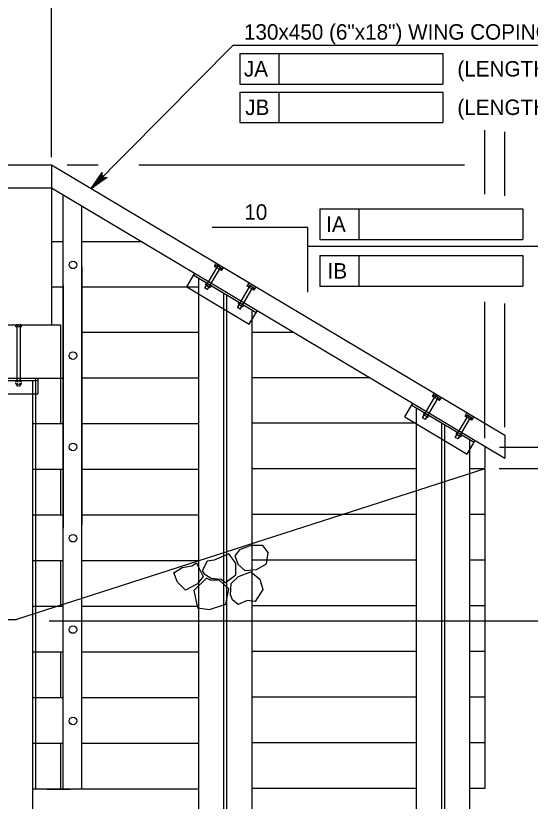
# Model space of a CAD drawing. Extents: x 635440 to 640306, y 296653 to 298484.
# Drawn here: x 639686.1 to 639785.9, y 297346.1 to 297498.4 of the extents above; entities that cross this region are included whole.
import ezdxf

# ---------------------------------------------------------------- set-up
doc = ezdxf.new("R2010")
doc.units = 0
for name, color, linetype in [('3', 7, 'Continuous'), ('4', 7, 'Continuous'), ('5', 7, 'Continuous'), ('8', 7, 'Continuous')]:
    doc.layers.add(name, color=color, linetype=linetype)

# ---------------------------------------------------------------- blocks, each defined once
blk = doc.blocks.new('ROCK')
at = {"layer": '4'}
for points in [[(2.36725, 1.088), (2.2065, 0.82625), (2.378625, 0.506625), (2.66975, 0.3095), (3.128875, 0.403375), (3.48475, 0.6775), (3.4915, 1.123375), (3.25625, 1.36725), (2.783625, 1.308375)], [(1.10175, -0.02725), (1.4015, -0.159125), (1.78825, -0.148875), (1.980875, -0.266), (2.343375, 0.09475), (2.27875, 0.5505), (1.969375, 0.883), (1.4225, 0.553625), (1.152875, 0.479), (1.0105, 0.082)], [(0.74675, 0.359875), (0.882, 0.16), (1.072875, -0.144), (0.892, -0.457375), (0.448125, -0.758625), (0.1, -0.49325), (-0.095, -0.146375), (0.202875, 0.1025), (0.579125, 0.219875)], [(2.231375, -0.71725), (2.2025, -0.266375), (2.45475, 0.037125), (2.9085, 0.28875), (3.2995, 0.047625), (3.46875, -0.344), (3.231625, -0.855), (2.92, -0.860375), (2.5765, -1.054625), (2.340375, -0.904375)], [(1.2085, -0.192875), (0.778375, -0.737625), (1.008375, -1.391375), (1.48725, -1.396875), (2.09825, -1.106625), (2.133375, -0.486375), (1.723125, -0.203375), (1.37425, -0.239875)]]:
    blk.add_lwpolyline(points, close=True, dxfattribs=at)

msp = doc.modelspace()

# ---------------------------------------------------------------- linework, layer by layer
at = {"layer": '3'}
for p, q in [((639669.62, 297469.49), (639693.04, 297469.49)), ((639693.04, 297469.49), (639780.97, 297417.06)), ((639693.04, 297469.49), (639693.04, 297465.06)), ((639647.14, 297465.06), (639693.04, 297465.06)), ((639693.04, 297465.06), (639780.97, 297412.63)), ((639693.04, 297465.06), (639693.04, 297438.49)), ((639695.28, 297384.23), (639695.28, 297463.72)), ((639698.92, 297385.4), (639698.92, 297461.55)), ((639695.28, 297454.59), (639693.04, 297454.59)), ((639710.61, 297454.59), (639698.92, 297454.59)), ((639722.75, 297445.62), (639725.08, 297449.56)), ((639724.67, 297449.8), (639725.03, 297450.42)), ((639726.01, 297449), (639724.67, 297449.8)), ((639724.86, 297449.68), (639725.03, 297449.95)), ((639725.25, 297449.81), (639725.09, 297449.55)), ((639725.19, 297449.97), (639725.91, 297449.55)), ((639725.73, 297449.54), (639725.57, 297449.27)), ((639726.01, 297449), (639726.38, 297449.62)), ((639719.28, 297445.84), (639720.85, 297448.48)), ((639723.28, 297445.31), (639725.61, 297449.24)), ((639725.82, 297449.12), (639725.97, 297449.39)), ((639723.08, 297446.66), (639722.92, 297446.38)), ((639723.15, 297446.25), (639723.31, 297446.52)), ((639730.97, 297445.97), (639731.33, 297446.59)), ((639695.28, 297445.8), (639693.04, 297445.8)), ((639719.34, 297445.8), (639698.92, 297445.8)), ((639719.28, 297445.84), (639731.38, 297438.62)), ((639723.28, 297445.31), (639722.75, 297445.62)), ((639722.98, 297446.23), (639723.7, 297445.81)), ((639723.62, 297445.97), (639723.78, 297446.24)), ((639724.03, 297446.1), (639723.87, 297445.83)), ((639729.08, 297441.85), (639731.38, 297445.73)), ((639729.61, 297441.54), (639731.91, 297445.42)), ((639732.32, 297445.18), (639730.97, 297445.97)), ((639731.16, 297445.85), (639731.33, 297446.13)), ((639731.55, 297445.99), (639731.39, 297445.72)), ((639731.49, 297446.15), (639732.21, 297445.72)), ((639732.03, 297445.71), (639731.87, 297445.44)), ((639732.12, 297445.29), (639732.27, 297445.57)), ((639732.32, 297445.18), (639732.68, 297445.79)), ((639721.52, 297444.5), (639721.52, 297391.27)), ((639729.61, 297441.54), (639729.08, 297441.85)), ((639729.41, 297442.88), (639729.25, 297442.61)), ((639729.31, 297442.46), (639730.03, 297442.04)), ((639729.48, 297442.48), (639729.64, 297442.75)), ((639729.95, 297442.2), (639730.11, 297442.47)), ((639730.36, 297442.33), (639730.2, 297442.05)), ((639731.38, 297438.62), (639732.95, 297441.27)), ((639731.85, 297439.43), (639731.85, 297396.01)), ((639644.18, 297438.49), (639694.77, 297438.49)), ((639686.1, 297438.09), (639686.1, 297438.39)), ((639687.17, 297438.09), (639686.1, 297438.09)), ((639686.22, 297438.49), (639687.03, 297438.49)), ((639686.26, 297438.48), (639686.26, 297438.48)), ((639686.27, 297438.48), (639686.27, 297438.48)), ((639686.29, 297438.48), (639686.29, 297438.48)), ((639686.3, 297438.48), (639686.3, 297438.48)), ((639686.3, 297438.47), (639686.3, 297438.47)), ((639686.3, 297438.09), (639686.3, 297427.59)), ((639686.31, 297438.47), (639686.31, 297438.47)), ((639686.32, 297438.48), (639686.32, 297438.48)), ((639686.32, 297438.45), (639686.32, 297438.45)), ((639686.33, 297438.48), (639686.33, 297438.48)), ((639686.33, 297438.47), (639686.33, 297438.47)), ((639686.33, 297438.45), (639686.33, 297438.45)), ((639686.34, 297438.47), (639686.34, 297438.47)), ((639686.34, 297438.44), (639686.34, 297438.44)), ((639686.35, 297438.48), (639686.35, 297438.48)), ((639686.35, 297438.47), (639686.35, 297438.47)), ((639686.35, 297438.45), (639686.35, 297438.45)), ((639686.35, 297438.44), (639686.35, 297438.44)), ((639686.35, 297438.42), (639686.35, 297438.42)), ((639686.35, 297438.41), (639686.35, 297438.41)), ((639686.36, 297438.48), (639686.36, 297438.48)), ((639686.36, 297438.47), (639686.36, 297438.47)), ((639686.36, 297438.45), (639686.36, 297438.45)), ((639686.36, 297438.44), (639686.36, 297438.44)), ((639686.36, 297438.42), (639686.36, 297438.42)), ((639686.36, 297438.41), (639686.36, 297438.41)), ((639686.36, 297438.39), (639686.36, 297438.09)), ((639686.37, 297438.47), (639686.37, 297438.47)), ((639686.37, 297438.44), (639686.37, 297438.44)), ((639686.37, 297438.41), (639686.37, 297438.41)), ((639686.38, 297438.48), (639686.38, 297438.48)), ((639686.38, 297438.45), (639686.38, 297438.45)), ((639686.38, 297438.42), (639686.38, 297438.42)), ((639686.39, 297438.48), (639686.39, 297438.48)), ((639686.39, 297438.47), (639686.39, 297438.47)), ((639686.39, 297438.45), (639686.39, 297438.45)), ((639686.39, 297438.44), (639686.39, 297438.44)), ((639686.39, 297438.42), (639686.39, 297438.42)), ((639686.4, 297438.47), (639686.4, 297438.47)), ((639686.4, 297438.44), (639686.4, 297438.44)), ((639686.41, 297438.48), (639686.41, 297438.48)), ((639686.41, 297438.45), (639686.41, 297438.45)), ((639686.42, 297438.48), (639686.42, 297438.48)), ((639686.42, 297438.47), (639686.42, 297438.47)), ((639686.42, 297438.45), (639686.42, 297438.45)), ((639686.42, 297438.44), (639686.42, 297438.44)), ((639686.43, 297438.47), (639686.43, 297438.47)), ((639686.44, 297438.48), (639686.44, 297438.48)), ((639686.44, 297438.45), (639686.44, 297438.45)), ((639686.45, 297438.48), (639686.45, 297438.48)), ((639686.45, 297438.47), (639686.45, 297438.47)), ((639686.45, 297438.45), (639686.45, 297438.45)), ((639686.46, 297438.47), (639686.46, 297438.47)), ((639686.47, 297438.48), (639686.47, 297438.48)), ((639686.48, 297438.48), (639686.48, 297438.48)), ((639686.48, 297438.47), (639686.48, 297438.47)), ((639686.49, 297438.47), (639686.49, 297438.47)), ((639686.5, 297438.48), (639686.5, 297438.48)), ((639686.51, 297438.48), (639686.51, 297438.48)), ((639686.53, 297438.48), (639686.53, 297438.48)), ((639686.54, 297438.48), (639686.54, 297438.48)), ((639686.56, 297438.48), (639686.56, 297438.48)), ((639686.69, 297438.48), (639686.69, 297438.48)), ((639686.7, 297438.48), (639686.7, 297438.48)), ((639686.72, 297438.48), (639686.72, 297438.48)), ((639686.73, 297438.48), (639686.73, 297438.48)), ((639686.75, 297438.48), (639686.75, 297438.48)), ((639686.76, 297438.48), (639686.76, 297438.48)), ((639686.76, 297438.47), (639686.76, 297438.47)), ((639686.77, 297438.47), (639686.77, 297438.47)), ((639686.78, 297438.48), (639686.78, 297438.48)), ((639686.79, 297438.48), (639686.79, 297438.48)), ((639686.79, 297438.47), (639686.79, 297438.47)), ((639686.79, 297438.45), (639686.79, 297438.45)), ((639686.8, 297438.47), (639686.8, 297438.47)), ((639686.81, 297438.48), (639686.81, 297438.48)), ((639686.81, 297438.45), (639686.81, 297438.45)), ((639686.82, 297438.48), (639686.82, 297438.48)), ((639686.82, 297438.47), (639686.82, 297438.47)), ((639686.82, 297438.45), (639686.82, 297438.45)), ((639686.83, 297438.47), (639686.83, 297438.47)), ((639686.83, 297438.44), (639686.83, 297438.44)), ((639686.84, 297438.48), (639686.84, 297438.48)), ((639686.84, 297438.45), (639686.84, 297438.45)), ((639686.85, 297438.48), (639686.85, 297438.48)), ((639686.85, 297438.47), (639686.85, 297438.47)), ((639686.85, 297438.45), (639686.85, 297438.45)), ((639686.85, 297438.44), (639686.85, 297438.44)), ((639686.85, 297438.42), (639686.85, 297438.42)), ((639686.86, 297438.47), (639686.86, 297438.47)), ((639686.86, 297438.44), (639686.86, 297438.44)), ((639686.87, 297438.48), (639686.87, 297438.48)), ((639686.87, 297438.45), (639686.87, 297438.45)), ((639686.87, 297438.42), (639686.87, 297438.42)), ((639686.88, 297438.48), (639686.88, 297438.48)), ((639686.88, 297438.47), (639686.88, 297438.47)), ((639686.88, 297438.45), (639686.88, 297438.45)), ((639686.88, 297438.44), (639686.88, 297438.44)), ((639686.88, 297438.42), (639686.88, 297438.42)), ((639686.88, 297438.41), (639686.88, 297438.41)), ((639686.89, 297438.47), (639686.89, 297438.47)), ((639686.89, 297438.44), (639686.89, 297438.44)), ((639686.89, 297438.41), (639686.89, 297438.41)), ((639686.89, 297438.39), (639686.89, 297438.09)), ((639686.9, 297438.48), (639686.9, 297438.48)), ((639686.9, 297438.47), (639686.9, 297438.47)), ((639686.9, 297438.45), (639686.9, 297438.45)), ((639686.9, 297438.44), (639686.9, 297438.44)), ((639686.9, 297438.42), (639686.9, 297438.42)), ((639686.91, 297438.48), (639686.91, 297438.48)), ((639686.91, 297438.45), (639686.91, 297438.45)), ((639686.92, 297438.47), (639686.92, 297438.47)), ((639686.93, 297438.48), (639686.93, 297438.48)), ((639686.93, 297438.47), (639686.93, 297438.47)), ((639686.93, 297438.45), (639686.93, 297438.45)), ((639686.94, 297438.48), (639686.94, 297438.48)), ((639686.95, 297438.47), (639686.95, 297438.47)), ((639686.96, 297438.48), (639686.96, 297438.48)), ((639686.96, 297438.09), (639686.96, 297427.59)), ((639686.97, 297438.48), (639686.97, 297438.48)), ((639686.99, 297438.48), (639686.99, 297438.48)), ((639687.17, 297438.09), (639687.17, 297438.39)), ((639694.77, 297438.49), (639694.77, 297419.29)), ((639721.52, 297437.01), (639698.92, 297437.01)), ((639740.12, 297436.99), (639731.85, 297436.99)), ((639731.85, 297430.73), (639731.85, 297426.04)), ((639645.73, 297428.15), (639695.28, 297428.15)), ((639689.93, 297428.15), (639689.93, 297348.42)), ((639690.35, 297428.15), (639690.35, 297425.07)), ((639721.52, 297428.15), (639698.92, 297428.15)), ((639754.86, 297428.2), (639731.85, 297428.2)), ((639686.11, 297427.35), (639686.11, 297427.5)), ((639686.11, 297427.04), (639686.11, 297427.2)), ((639686.23, 297427.59), (639687.04, 297427.59)), ((639686.23, 297426.95), (639686.54, 297426.95)), ((639686.3, 297427.77), (639686.54, 297427.77)), ((639686.3, 297426.95), (639686.3, 297426.62)), ((639686.3, 297426.62), (639686.54, 297426.62)), ((639686.36, 297427.5), (639686.36, 297427.35)), ((639686.36, 297427.2), (639686.36, 297427.04)), ((639686.69, 297426.95), (639687.04, 297426.95)), ((639686.69, 297426.62), (639686.96, 297426.62)), ((639686.72, 297427.77), (639686.96, 297427.77)), ((639686.9, 297427.5), (639686.9, 297427.35)), ((639686.9, 297427.2), (639686.9, 297427.04)), ((639686.96, 297426.95), (639686.96, 297426.62)), ((639687.17, 297427.35), (639687.17, 297427.5)), ((639687.17, 297427.04), (639687.17, 297427.2)), ((639766.93, 297424.6), (639767.29, 297425.22)), ((639677.97, 297425.07), (639690.35, 297425.07)), ((639689.32, 297425.07), (639689.32, 297382.73)), ((639765.01, 297420.42), (639767.34, 297424.36)), ((639765.54, 297420.11), (639767.87, 297424.05)), ((639768.28, 297423.8), (639766.93, 297424.6)), ((639767.13, 297424.48), (639767.29, 297424.75)), ((639767.51, 297424.61), (639767.36, 297424.35)), ((639767.45, 297424.77), (639768.17, 297424.35)), ((639767.99, 297424.34), (639767.83, 297424.07)), ((639768.08, 297423.92), (639768.24, 297424.19)), ((639768.28, 297423.8), (639768.64, 297424.42)), ((639761.54, 297420.64), (639763.12, 297423.28)), ((639761.54, 297420.64), (639773.64, 297413.42)), ((639765.34, 297421.46), (639765.18, 297421.19)), ((639765.24, 297421.04), (639765.96, 297420.61)), ((639765.41, 297421.05), (639765.57, 297421.32)), ((639765.89, 297420.77), (639766.04, 297421.04)), ((639766.29, 297420.9), (639766.13, 297420.63)), ((639771.34, 297416.65), (639773.64, 297420.53)), ((639773.23, 297420.77), (639773.59, 297421.39)), ((639774.58, 297419.98), (639773.23, 297420.77)), ((639773.43, 297420.65), (639773.59, 297420.93)), ((639773.82, 297420.79), (639773.66, 297420.52)), ((639773.75, 297420.95), (639774.47, 297420.52)), ((639774.58, 297419.98), (639774.94, 297420.59)), ((639695.28, 297419.29), (639689.32, 297419.29)), ((639721.52, 297419.29), (639698.92, 297419.29)), ((639763.78, 297419.41), (639731.85, 297419.41)), ((639763.78, 297419.3), (639763.78, 297406.28)), ((639765.54, 297420.11), (639765.01, 297420.42)), ((639771.88, 297416.34), (639774.17, 297420.22)), ((639774.29, 297420.51), (639774.13, 297420.24)), ((639774.38, 297420.1), (639774.54, 297420.37)), ((639771.67, 297417.68), (639771.51, 297417.41)), ((639771.74, 297417.28), (639771.9, 297417.55)), ((639771.88, 297416.34), (639771.34, 297416.65)), ((639771.57, 297417.26), (639772.3, 297416.84)), ((639772.22, 297417), (639772.38, 297417.27)), ((639772.63, 297417.13), (639772.46, 297416.85)), ((639773.64, 297413.42), (639775.21, 297416.07)), ((639780.97, 297417.06), (639780.97, 297412.63)), ((639777.07, 297414.96), (639777.07, 297410.73)), ((639774.12, 297414.23), (639774.12, 297409.65)), ((639777.07, 297410.55), (639686.26, 297381.33)), ((639695.28, 297410.43), (639689.32, 297410.43)), ((639694.77, 297410.43), (639694.77, 297401.57)), ((639721.52, 297410.43), (639698.92, 297410.43)), ((639763.78, 297410.55), (639731.85, 297410.55)), ((639777.07, 297410.55), (639774.12, 297410.55)), ((639777.07, 297410.55), (639777.07, 297348.54)), ((639774.12, 297409.72), (639774.12, 297337.09)), ((639763.78, 297406.28), (639763.78, 297336.81)), ((639695.28, 297401.57), (639689.32, 297401.57)), ((639721.52, 297401.57), (639698.92, 297401.57)), ((639749.54, 297401.69), (639731.86, 297401.69)), ((639763.78, 297401.69), (639749.54, 297401.69)), ((639777.07, 297401.69), (639774.12, 297401.69)), ((639731.85, 297396.01), (639731.85, 297337.09)), ((639695.28, 297392.72), (639689.32, 297392.72)), ((639694.77, 297392.72), (639694.77, 297383.86)), ((639721.52, 297392.72), (639698.92, 297392.72)), ((639763.78, 297392.84), (639731.85, 297392.84)), ((639777.07, 297392.84), (639774.12, 297392.84)), ((639721.52, 297391.27), (639721.52, 297336.81)), ((639695.28, 297348.42), (639695.28, 297384.23)), ((639698.92, 297348.42), (639698.92, 297385.4)), ((639763.78, 297383.98), (639731.85, 297383.98)), ((639777.07, 297383.98), (639774.12, 297383.98)), ((639695.28, 297383.86), (639689.32, 297383.86)), ((639689.32, 297382.73), (639689.32, 297336.96)), ((639721.52, 297383.86), (639698.92, 297383.86)), ((639656.78, 297381.33), (639686.26, 297381.33)), ((639695.28, 297375), (639689.32, 297375)), ((639694.77, 297375), (639694.77, 297366.14)), ((639721.52, 297375), (639698.92, 297375)), ((639763.78, 297375.12), (639731.85, 297375.12)), ((639777.07, 297375.12), (639774.12, 297375.12)), ((639695.28, 297366.14), (639689.32, 297366.14)), ((639721.52, 297366.14), (639698.92, 297366.14)), ((639763.78, 297366.26), (639731.85, 297366.26)), ((639777.07, 297366.26), (639774.12, 297366.26)), ((639695.28, 297357.28), (639689.32, 297357.28)), ((639694.77, 297357.28), (639694.77, 297348.42)), ((639721.52, 297357.28), (639698.92, 297357.28)), ((639763.78, 297357.4), (639731.85, 297357.4)), ((639777.07, 297357.4), (639774.12, 297357.4)), ((639721.52, 297348.42), (639689.32, 297348.42)), ((639692.2, 297348.42), (639696.63, 297348.42)), ((639763.78, 297348.54), (639731.85, 297348.54)), ((639777.07, 297348.54), (639774.12, 297348.54))]:
    msp.add_line(p, q, dxfattribs=at)
for centre in [(639697.18, 297450.12), (639697.18, 297432.53), (639697.18, 297414.81), (639697.18, 297397.1), (639697.18, 297379.38), (639697.18, 297361.66)]:
    msp.add_circle(centre, 0.738, dxfattribs=at)
for centre, radius, start, end in [((639725.12, 297449.85), 0.139, 346.8498, 131.9461), ((639725.32, 297449.38), 0.438, 20.448, 98.348), ((639725.82, 297449.42), 0.153, 61.225, 128.111), ((639725.82, 297449.42), 0.153, 350.6849, 61.225), ((639723.05, 297446.35), 0.139, 166.9183, 312.0147), ((639723.56, 297446.4), 0.438, 200.5165, 278.4165), ((639723.77, 297445.94), 0.153, 170.7534, 237.6394), ((639723.77, 297445.94), 0.153, 237.6394, 308.1795), ((639731.42, 297446.02), 0.139, 346.8498, 131.9461), ((639731.62, 297445.56), 0.438, 20.448, 98.348), ((639732.13, 297445.59), 0.153, 61.225, 128.111), ((639732.13, 297445.59), 0.153, 350.6849, 61.225), ((639729.39, 297442.58), 0.139, 166.9183, 312.0147), ((639729.89, 297442.63), 0.438, 200.5165, 278.4165), ((639730.11, 297442.17), 0.153, 170.7534, 237.6394), ((639730.11, 297442.17), 0.153, 237.6394, 308.1795), ((639686.23, 297438.35), 0.135, 17.4518, 162.5482), ((639686.62, 297438.06), 0.424, 51.05, 128.95), ((639687.03, 297438.34), 0.148, 91.8271, 158.7131), ((639687.03, 297438.34), 0.148, 21.2869, 91.8271), ((639686.24, 297427.46), 0.135, 17.4518, 162.5482), ((639686.24, 297427.08), 0.135, 197.4518, 342.5482), ((639686.63, 297427.17), 0.424, 51.05, 128.95), ((639686.63, 297427.37), 0.424, 231.05, 257.4918), ((639686.63, 297427.37), 0.424, 277.8862, 308.95), ((639687.04, 297427.44), 0.148, 91.8271, 158.7131), ((639687.04, 297427.09), 0.148, 201.2869, 268.1729), ((639687.04, 297427.44), 0.148, 21.2869, 91.8271), ((639687.04, 297427.09), 0.148, 268.1729, 338.7131), ((639767.38, 297424.65), 0.139, 346.8498, 131.9461), ((639767.58, 297424.18), 0.438, 20.448, 98.348), ((639768.09, 297424.22), 0.153, 61.225, 128.111), ((639768.09, 297424.22), 0.153, 350.6849, 61.225), ((639765.32, 297421.15), 0.139, 166.9183, 312.0147), ((639765.82, 297421.2), 0.438, 200.5165, 278.4165), ((639766.04, 297420.75), 0.153, 170.7534, 237.6394), ((639766.04, 297420.75), 0.153, 237.6394, 308.1795), ((639773.68, 297420.82), 0.139, 346.8498, 131.9461), ((639773.88, 297420.36), 0.438, 20.448, 98.348), ((639774.39, 297420.39), 0.153, 61.225, 128.111), ((639774.39, 297420.39), 0.153, 350.6849, 61.225), ((639771.65, 297417.38), 0.139, 166.9183, 312.0147), ((639772.15, 297417.43), 0.438, 200.5165, 278.4165), ((639772.37, 297416.97), 0.153, 170.7534, 237.6394), ((639772.37, 297416.97), 0.153, 237.6394, 308.1795)]:
    msp.add_arc(centre, radius, start, end, dxfattribs=at)
at = {"layer": '4'}
for p, q in [((639693.04, 297471.03), (639693.04, 297514.88)), ((639700.73, 297464.9), (639728.25, 297492.76)), ((639728.25, 297492.76), (639821.94, 297492.76)), ((639729.56, 297491.11), (639768.93, 297491.11)), ((639729.56, 297491.11), (639729.56, 297485.2)), ((639737.12, 297491.11), (639737.12, 297485.2)), ((639768.93, 297491.11), (639768.93, 297485.2)), ((639729.56, 297485.2), (639768.93, 297485.2)), ((639729.56, 297483.64), (639768.93, 297483.64)), ((639729.56, 297483.64), (639729.56, 297477.74)), ((639737.12, 297483.64), (639737.12, 297477.74)), ((639768.93, 297483.64), (639768.93, 297477.74)), ((639729.56, 297477.74), (639768.93, 297477.74)), ((639777.07, 297463.83), (639777.07, 297476.22)), ((639780.97, 297463.51), (639780.97, 297475.9)), ((639696.09, 297469.49), (639702.08, 297469.49)), ((639709.93, 297469.49), (639773.14, 297469.49)), ((639745.1, 297460.97), (639784.47, 297460.97)), ((639745.1, 297460.97), (639745.1, 297455.06)), ((639752.66, 297460.97), (639752.66, 297455.06)), ((639784.47, 297460.97), (639784.47, 297455.06)), ((639742.75, 297457.36), (639724.17, 297457.36)), ((639742.75, 297444.82), (639742.75, 297457.36)), ((639745.1, 297455.06), (639784.47, 297455.06)), ((639817.6, 297453.7), (639742.75, 297453.7)), ((639745.1, 297451.91), (639784.47, 297451.91)), ((639745.1, 297451.91), (639745.1, 297446)), ((639752.66, 297451.91), (639752.66, 297446)), ((639784.47, 297451.91), (639784.47, 297446)), ((639698.92, 297449.77), (639698.92, 297399.69)), ((639695.28, 297446.13), (639695.28, 297399.05)), ((639745.1, 297446), (639784.47, 297446)), ((639777.07, 297416.5), (639777.07, 297442.96)), ((639780.97, 297418.65), (639780.97, 297442.64)), ((639779.9, 297414.74), (639881.35, 297414.74)), ((639788.12, 297410.55), (639779.83, 297410.55)), ((639788.12, 297380.97), (639692.54, 297380.97))]:
    msp.add_line(p, q, dxfattribs=at)
msp.add_lwpolyline([(639700.73, 297464.9), (639702.86, 297468.05), (639702.8, 297467.7), (639702.87, 297467.42), (639703.02, 297467.21), (639703.23, 297467.07), (639703.51, 297467), (639703.85, 297467.06), (639700.73, 297464.9), (639703.51, 297467), (639703.23, 297467.07), (639700.73, 297464.9), (639703.02, 297467.21), (639702.87, 297467.42), (639700.73, 297464.9), (639702.8, 297467.7)], dxfattribs=at)
msp.add_lwpolyline([(639703.06, 297466.59), (639702.39, 297467.25), (639700.74, 297464.9)], close=True, dxfattribs=at)
at = {"layer": '8'}
for p, q in [((639720.64, 297448.11), (639732.74, 297440.9)), ((639721.52, 297447.59), (639721.52, 297444.5)), ((639721.52, 297445.8), (639719.34, 297445.8)), ((639726.39, 297444.68), (639726.39, 297336.79)), ((639726.98, 297444.33), (639726.98, 297336.42)), ((639731.85, 297441.43), (639731.85, 297439.42)), ((639677.97, 297427.66), (639690.35, 297427.66)), ((639689.32, 297427.66), (639689.32, 297425.07)), ((639762.9, 297422.91), (639775, 297415.7)), ((639763.78, 297422.39), (639763.78, 297419.3)), ((639768.65, 297419.49), (639768.65, 297336.79)), ((639769.24, 297419.13), (639769.24, 297336.42)), ((639774.12, 297416.23), (639774.12, 297414.23))]:
    msp.add_line(p, q, dxfattribs=at)

# ---------------------------------------------------------------- block references
at = {"layer": '4', "xscale": 4.921475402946, "yscale": 4.921475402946, "rotation": -7.300632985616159}
msp.add_blockref('ROCK', (639717.28, 297391.01), dxfattribs=at)

# ---------------------------------------------------------------- texts
at = {"layer": '4'}
for s, height, p in [('JA', 3, (639730.34, 297486.65)), ('(LENGTH) WINGWALL A', 3.0001, (639771.75, 297486.65)), ('JB', 3, (639730.6, 297479.19)), ('(LENGTH) WINGWALL B', 3.0001, (639771.75, 297479.19)), ('10', 3, (639730.42, 297458.86))]:
    msp.add_text(s, height=height, dxfattribs=at).set_placement(p)
for s, p in [('IA', (639746.31, 297456.52)), ('IB', (639746.57, 297447.45))]:
    msp.add_text(s, height=3, rotation=359.9382, dxfattribs=at).set_placement(p)
at = {"layer": '5'}
msp.add_text('130x450 (6"x18") WING COPING', height=3.0001, dxfattribs=at).set_placement((639730.35, 297493.8))

doc.saveas('drawing.dxf')
